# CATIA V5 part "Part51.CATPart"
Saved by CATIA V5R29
Part number: Motor shaft
Revision: ANY
Definition: UNKNOWN
Nomenclature: Motor shaft
Source: Unknown
Bounding box of the stored display mesh (mm): x -5.25 to 5.25, y -5.25 to 5.25, z -30 to 30
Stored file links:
  C:\Users\Administrator\Desktop\프로젝트\Gripper\Part51.CATPart
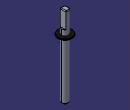
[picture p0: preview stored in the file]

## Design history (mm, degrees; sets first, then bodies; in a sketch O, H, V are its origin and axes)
Body1 "Fillet1" (main body)
  Solid1: solid without history
Body2 "Chamfer1"
  Solid2: solid without history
